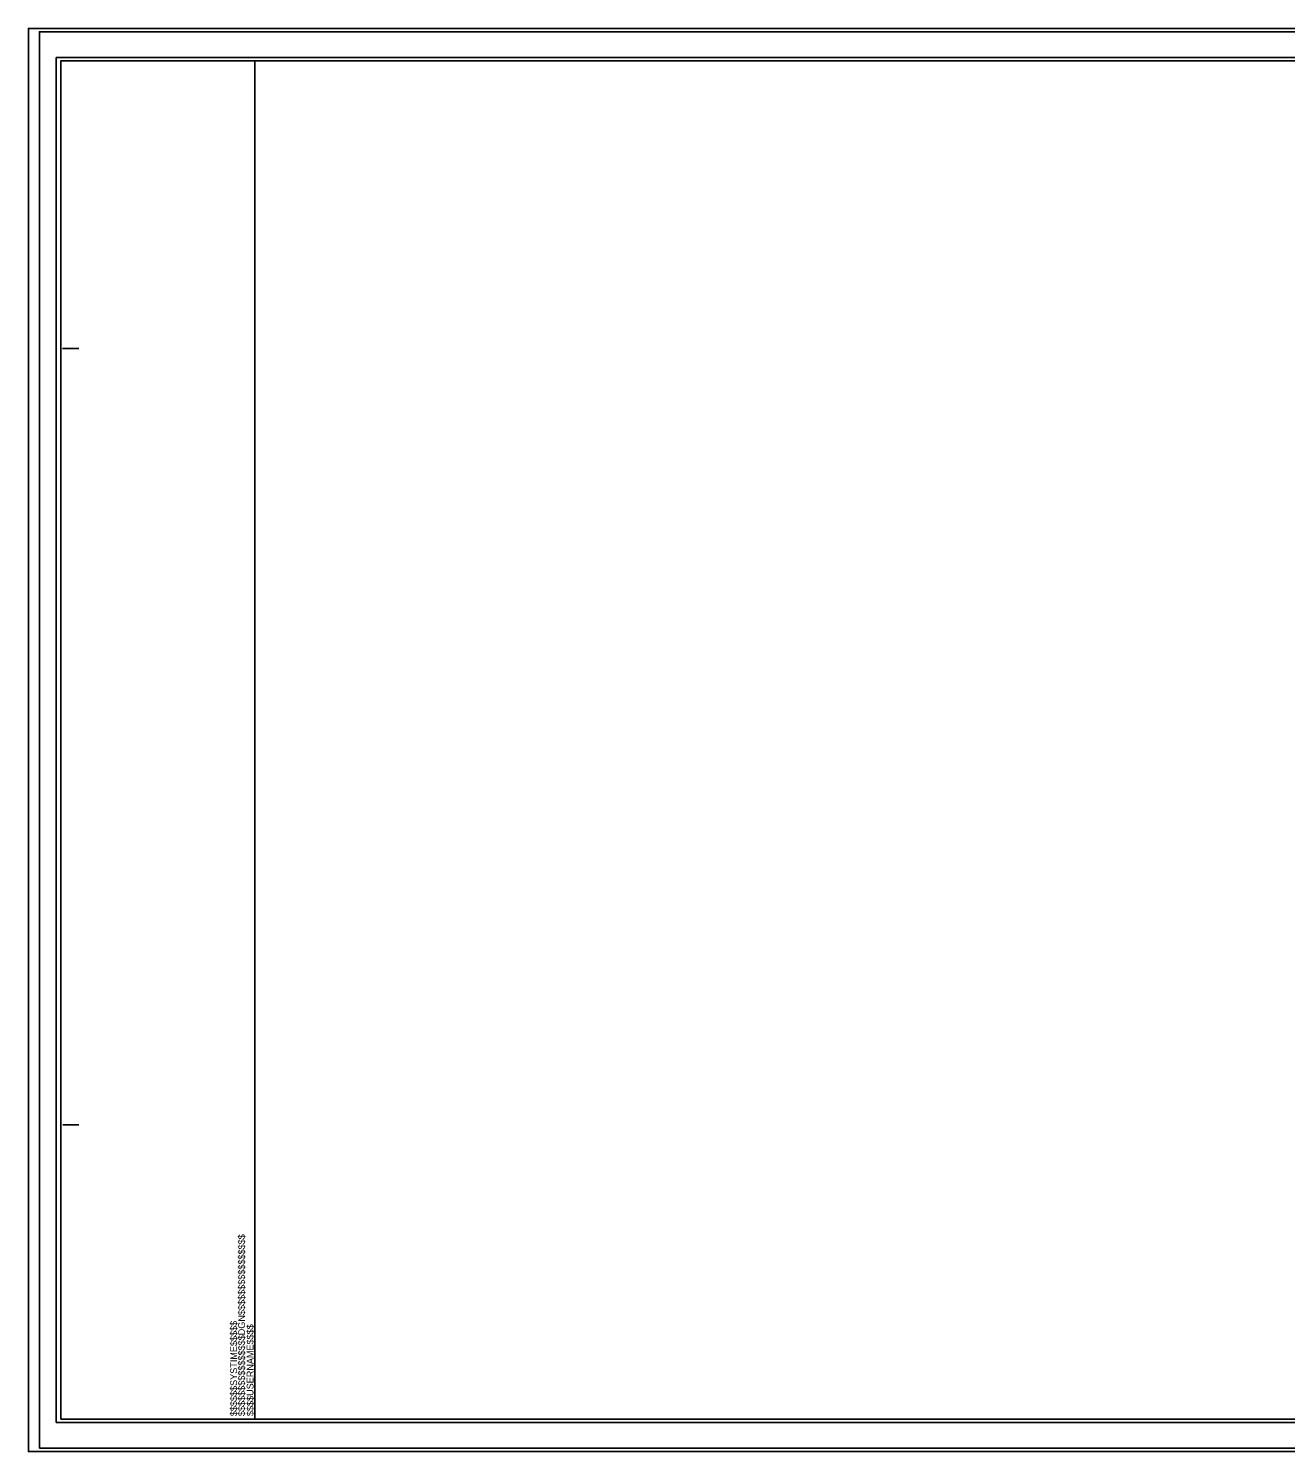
# Model space of a CAD drawing. Extents: x 1852853 to 1854796, y 258638 to 259738.
# Drawn here: x 1852853 to 1853825, y 258638 to 259738 of the extents above; entities that cross this region are included whole.
import ezdxf

# ---------------------------------------------------------------- set-up
doc = ezdxf.new("R2010")
doc.units = 0
for name, color, linetype in [('Old_Level_46', 7, 'Continuous'), ('Old_Level_62', 7, 'Continuous'), ('Old_Level_63', 7, 'Continuous'), ('Sheet Clip Boundary CELL', 7, 'Continuous'), ('Sheet Cutting Line CELL', 7, 'Continuous'), ('Sheet Plan CELL', 7, 'Continuous'), ('Sheet Plot Border Inside CELL', 7, 'Continuous'), ('Sheet Plot Border Outside CELL', 7, 'Continuous')]:
    doc.layers.add(name, color=color, linetype=linetype)

msp = doc.modelspace()

# ---------------------------------------------------------------- linework, layer by layer
at = {"layer": 'Old_Level_46'}
msp.add_line((1853028.1, 259713.5), (1853028.1, 259713.5), dxfattribs=at)
at = {"layer": 'Old_Level_62'}
msp.add_line((1852878.1, 258663.5), (1852878.1, 258663.5), dxfattribs=at)
msp.add_lwpolyline([(1852878.1, 258663.5), (1854528.1, 258663.5), (1854528.1, 259713.5), (1852878.1, 259713.5)], close=True, dxfattribs=at)
at = {"layer": 'Old_Level_63'}
msp.add_line((1852853.1, 258638.5), (1852853.1, 258638.5), dxfattribs=at)
msp.add_lwpolyline([(1854553.1, 259738.5), (1852853.1, 259738.5), (1852853.1, 258638.5), (1854553.1, 258638.5)], close=True, dxfattribs=at)
at = {"layer": 'Sheet Clip Boundary CELL'}
msp.add_lwpolyline([(1853028.1, 258663.5), (1854528.1, 258663.5), (1854528.1, 259480.4), (1854328, 259480.4), (1854328, 259713.5), (1853028.1, 259713.5)], close=True, dxfattribs=at)
at = {"layer": 'Sheet Cutting Line CELL'}
for p, q in [((1854545.1, 259736), (1852861.6, 259736)), ((1852861.6, 259736), (1852861.6, 258641))]:
    msp.add_line(p, q, dxfattribs=at)
at = {"layer": 'Sheet Plan CELL'}
for p, q in [((1853028, 259713.5), (1853028, 259713.5)), ((1852879.5, 259491), (1852892, 259491)), ((1852879.6, 258891), (1852892.1, 258891)), ((1853028, 258663.5), (1853028, 258663.5))]:
    msp.add_line(p, q, dxfattribs=at)
msp.add_lwpolyline([(1854528.1, 259713.5), (1853028.1, 259713.5), (1853028.1, 258663.5), (1854528.1, 258663.5)], close=True, dxfattribs=at)
at = {"layer": 'Sheet Plot Border Inside CELL'}
msp.add_lwpolyline([(1852874.6, 258661), (1854540.6, 258661), (1854540.6, 259716), (1852874.6, 259716)], close=True, dxfattribs=at)
at = {"layer": 'Sheet Plot Border Outside CELL'}
msp.add_lwpolyline([(1852861.6, 258641), (1854545.1, 258641), (1854545.1, 259736), (1852861.6, 259736)], close=True, dxfattribs=at)

# ---------------------------------------------------------------- texts
at = {"layer": 'Sheet Plan CELL'}
for s, p in [('$$$$$$$$$$$$$$$$DGN$$$$$$$$$$$$$$$$', (1853020.4, 258665.9)), ('$$$$$$SYSTIME$$$$$', (1853014.3, 258665.8)), ('$$$$USERNAME$$$$', (1853027, 258665.9))]:
    msp.add_text(s, height=5.25, rotation=90, dxfattribs=at).set_placement(p)

doc.saveas('drawing.dxf')
